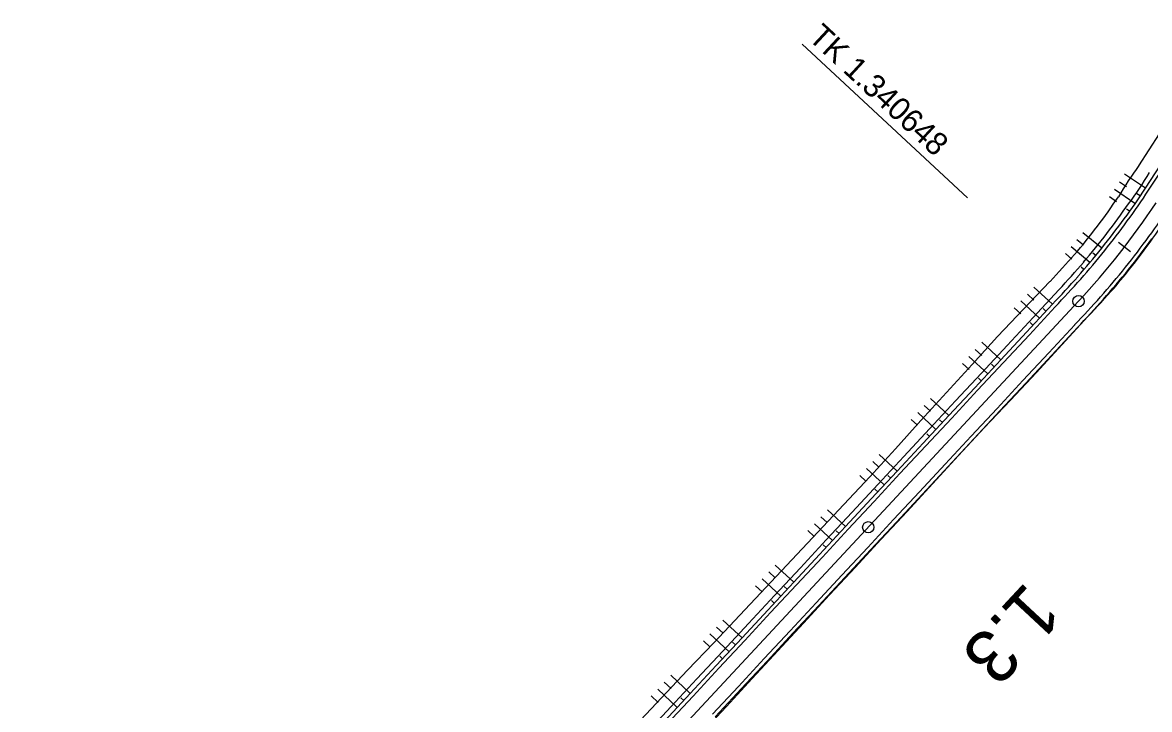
# Model space of a CAD drawing. Extents: x -481656 to -478728, y -1113199 to -1110710.
# Drawn here: x -479136.3 to -478987.9, y -1110857.1 to -1110766.6 of the extents above; entities that cross this region are included whole.
import ezdxf

# ---------------------------------------------------------------- set-up
doc = ezdxf.new("R2010")
doc.units = 0
for name, color, linetype in [('C5_HATCH_SLOPE_L', 7, 'Continuous'), ('C5_HATCH_SLOPE_R', 7, 'Continuous'), ('C5_HECTOMETRY', 7, 'Continuous'), ('C5_HLBODY', 7, 'Continuous'), ('C5_HRANA_TELESO', 7, 'Continuous'), ('C5_KORUNA', 7, 'Continuous'), ('C5_OSA', 7, 'Continuous'), ('C5_PRIKOP', 7, 'Continuous'), ('C5_STANICENI', 7, 'Continuous'), ('C5_ZPEVKRAJ', 7, 'Continuous')]:
    doc.layers.add(name, color=color, linetype=linetype)

msp = doc.modelspace()

# ---------------------------------------------------------------- linework, layer by layer
at = {"layer": 'C5_HATCH_SLOPE_L'}
for p, q in [((-478988.47, -1110788.42), (-478991.2, -1110786.61)), ((-478989.84, -1110790.47), (-478992.53, -1110788.62)), ((-478990.93, -1110788.27), (-478991.88, -1110787.64)), ((-478992.27, -1110790.25), (-478993.2, -1110789.6)), ((-478989.16, -1110789.46), (-478989.57, -1110789.18)), ((-478990.54, -1110791.47), (-478990.94, -1110791.19)), ((-478994.2, -1110796.36), (-478996.72, -1110794.34)), ((-478995.76, -1110798.24), (-478998.23, -1110796.16)), ((-478996.61, -1110795.96), (-478997.47, -1110795.26)), ((-478998.15, -1110797.78), (-478999, -1110797.05)), ((-478994.97, -1110797.3), (-478995.36, -1110796.99)), ((-478996.55, -1110799.17), (-478996.93, -1110798.84)), ((-479000.7, -1110803.73), (-479003.13, -1110801.48)), ((-479002.41, -1110805.56), (-479004.86, -1110803.28)), ((-479003.14, -1110803.17), (-479003.99, -1110802.38)), ((-479004.86, -1110804.99), (-479005.72, -1110804.19)), ((-479001.55, -1110804.65), (-479001.92, -1110804.3)), ((-479003.26, -1110806.48), (-479003.63, -1110806.14)), ((-479007.51, -1110811.06), (-479010, -1110808.74)), ((-479009.22, -1110812.89), (-479011.69, -1110810.59)), ((-479009.98, -1110810.47), (-479010.85, -1110809.67)), ((-479011.67, -1110812.31), (-479012.53, -1110811.51)), ((-479008.36, -1110811.97), (-479008.74, -1110811.63)), ((-479010.07, -1110813.8), (-479010.44, -1110813.46)), ((-479014.32, -1110818.38), (-479016.75, -1110816.12)), ((-479016.03, -1110820.21), (-479018.43, -1110817.97)), ((-479016.76, -1110817.82), (-479017.59, -1110817.05)), ((-479018.45, -1110819.66), (-479019.28, -1110818.89)), ((-479015.17, -1110819.29), (-479015.55, -1110818.95)), ((-479016.88, -1110821.13), (-479017.25, -1110820.78)), ((-479023.54, -1110825.17), (-479024.34, -1110824.43)), ((-479021.13, -1110825.7), (-479023.49, -1110823.51)), ((-479022.84, -1110827.53), (-479025.19, -1110825.35)), ((-479025.24, -1110827.01), (-479026.03, -1110826.27)), ((-479021.98, -1110826.62), (-479022.36, -1110826.27)), ((-479023.69, -1110828.45), (-479024.06, -1110828.1)), ((-479030.36, -1110832.48), (-479031.17, -1110831.73)), ((-479027.94, -1110833.02), (-479030.31, -1110830.82)), ((-479029.65, -1110834.86), (-479032.03, -1110832.64)), ((-479032.07, -1110834.3), (-479032.89, -1110833.54)), ((-479028.79, -1110833.94), (-479029.17, -1110833.59)), ((-479030.5, -1110835.77), (-479030.88, -1110835.42)), ((-479037.21, -1110839.77), (-479038.05, -1110838.99)), ((-479034.75, -1110840.35), (-479037.19, -1110838.08)), ((-479036.46, -1110842.18), (-479038.91, -1110839.9)), ((-479038.92, -1110841.59), (-479039.77, -1110840.8)), ((-479035.6, -1110841.26), (-479035.99, -1110840.91)), ((-479037.31, -1110843.09), (-479037.69, -1110842.74)), ((-479044.05, -1110847.06), (-479044.93, -1110846.25)), ((-479041.56, -1110847.67), (-479044.07, -1110845.34)), ((-479045.77, -1110848.88), (-479046.65, -1110848.06)), ((-479043.27, -1110849.5), (-479045.79, -1110847.16)), ((-479042.41, -1110848.59), (-479042.8, -1110848.23)), ((-479044.12, -1110850.42), (-479044.5, -1110850.06)), ((-479048.37, -1110854.99), (-479050.94, -1110852.6)), ((-479050.9, -1110854.35), (-479051.8, -1110853.51)), ((-479052.61, -1110856.17), (-479053.52, -1110855.32)), ((-479050.08, -1110856.82), (-479052.66, -1110854.42)), ((-479049.22, -1110855.91), (-479049.61, -1110855.55))]:
    msp.add_line(p, q, dxfattribs=at)
at = {"layer": 'C5_HATCH_SLOPE_R'}
for p, q in [((-478988.66, -1110796.55), (-478988.64, -1110796.57)), ((-478988.61, -1110796.59), (-478988.61, -1110796.59)), ((-478992.65, -1110801.54), (-478992.59, -1110801.59)), ((-478994.33, -1110803.47), (-478994.29, -1110803.5)), ((-478993.49, -1110802.51), (-478993.46, -1110802.53)), ((-478993.43, -1110802.55), (-478993.43, -1110802.55)), ((-478995.19, -1110804.41), (-478995.18, -1110804.43)), ((-478995.16, -1110804.44), (-478995.16, -1110804.44)), ((-478999.46, -1110809), (-478999.43, -1110809.02)), ((-479001.16, -1110810.83), (-479001.12, -1110810.87)), ((-479000.31, -1110809.92), (-479000.29, -1110809.93)), ((-479000.28, -1110809.95), (-479000.28, -1110809.95)), ((-479002.01, -1110811.75), (-479001.98, -1110811.77)), ((-479001.96, -1110811.79), (-479001.96, -1110811.79)), ((-479006.27, -1110816.32), (-479006.24, -1110816.35)), ((-479007.97, -1110818.15), (-479007.95, -1110818.17)), ((-479007.12, -1110817.24), (-479007.11, -1110817.25)), ((-479007.1, -1110817.26), (-479007.1, -1110817.26)), ((-479008.82, -1110819.07), (-479008.82, -1110819.07)), ((-479008.81, -1110819.08), (-479008.81, -1110819.08)), ((-479013.08, -1110823.65), (-479013.05, -1110823.67)), ((-479014.78, -1110825.48), (-479014.75, -1110825.51)), ((-479013.93, -1110824.56), (-479013.91, -1110824.57)), ((-479013.9, -1110824.59), (-479013.9, -1110824.59)), ((-479015.63, -1110826.39), (-479015.61, -1110826.41)), ((-479015.6, -1110826.43), (-479015.6, -1110826.43)), ((-479019.89, -1110830.97), (-479019.83, -1110831.02)), ((-479021.59, -1110832.8), (-479021.53, -1110832.86)), ((-479020.74, -1110831.89), (-479020.71, -1110831.91)), ((-479020.68, -1110831.94), (-479020.68, -1110831.94)), ((-479022.44, -1110833.72), (-479022.41, -1110833.75)), ((-479022.38, -1110833.77), (-479022.38, -1110833.77)), ((-479027.55, -1110839.21), (-479027.51, -1110839.24)), ((-479027.48, -1110839.27), (-479027.48, -1110839.27)), ((-479026.7, -1110838.29), (-479026.62, -1110838.36)), ((-479028.4, -1110840.12), (-479028.33, -1110840.19)), ((-479029.25, -1110841.04), (-479029.21, -1110841.07)), ((-479029.17, -1110841.11), (-479029.17, -1110841.11)), ((-479034.36, -1110846.53), (-479034.32, -1110846.57)), ((-479034.28, -1110846.61), (-479034.28, -1110846.61)), ((-479033.51, -1110845.62), (-479033.42, -1110845.69)), ((-479035.21, -1110847.45), (-479035.12, -1110847.52)), ((-479036.06, -1110848.36), (-479036.02, -1110848.4)), ((-479035.98, -1110848.44), (-479035.98, -1110848.44)), ((-479041.17, -1110853.85), (-479041.12, -1110853.9)), ((-479041.08, -1110853.94), (-479041.08, -1110853.94)), ((-479040.32, -1110852.94), (-479040.23, -1110853.02)), ((-479042.02, -1110854.77), (-479041.92, -1110854.85)), ((-479042.87, -1110855.69), (-479042.82, -1110855.73)), ((-479042.78, -1110855.77), (-479042.78, -1110855.77))]:
    msp.add_line(p, q, dxfattribs=at)
at = {"layer": 'C5_HECTOMETRY'}
msp.add_circle((-479024.94, -1110833.1), 0.75, dxfattribs=at)
at = {"layer": 'C5_HLBODY'}
msp.add_line((-479033.65, -1110769.49), (-479011.9, -1110789.71), dxfattribs=at)
msp.add_circle((-478997.26, -1110803.33), 0.75, dxfattribs=at)
at = {"layer": 'C5_HRANA_TELESO'}
for p, q in [((-478989.32, -1110785.48), (-478986.59, -1110781.28)), ((-479004.47, -1110804.34), (-479001.02, -1110800.72)), ((-479007.91, -1110807.97), (-479004.47, -1110804.34)), ((-478999.43, -1110809.02), (-478996.03, -1110805.36)), ((-479011.27, -1110811.67), (-479007.91, -1110807.97)), ((-479002.8, -1110812.72), (-478999.43, -1110809.02)), ((-479014.64, -1110815.37), (-479011.27, -1110811.67)), ((-479006.24, -1110816.35), (-479002.8, -1110812.72)), ((-479018, -1110819.06), (-479014.64, -1110815.37)), ((-479009.67, -1110819.99), (-479006.24, -1110816.35)), ((-479021.37, -1110822.76), (-479018, -1110819.06)), ((-479013.05, -1110823.67), (-479009.67, -1110819.99)), ((-479024.73, -1110826.46), (-479021.37, -1110822.76)), ((-479016.44, -1110827.34), (-479013.05, -1110823.67)), ((-479028.14, -1110830.12), (-479024.73, -1110826.46)), ((-479019.83, -1110831.02), (-479016.44, -1110827.34)), ((-479031.57, -1110833.76), (-479028.14, -1110830.12)), ((-479023.23, -1110834.69), (-479019.83, -1110831.02)), ((-479035, -1110837.4), (-479031.57, -1110833.76)), ((-479026.62, -1110838.36), (-479023.23, -1110834.69)), ((-479038.43, -1110841.03), (-479035, -1110837.4)), ((-479030.03, -1110842.02), (-479026.62, -1110838.36)), ((-479041.86, -1110844.67), (-479038.43, -1110841.03)), ((-479033.42, -1110845.69), (-479030.03, -1110842.02)), ((-479045.29, -1110848.31), (-479041.86, -1110844.67)), ((-479036.83, -1110849.36), (-479033.42, -1110845.69)), ((-479048.73, -1110851.94), (-479045.29, -1110848.31)), ((-479040.23, -1110853.02), (-479036.83, -1110849.36)), ((-479052.16, -1110855.58), (-479048.73, -1110851.94)), ((-479043.62, -1110856.69), (-479040.23, -1110853.02)), ((-479055.59, -1110859.22), (-479052.16, -1110855.58)), ((-479047.03, -1110860.35), (-479043.62, -1110856.69))]:
    msp.add_line(p, q, dxfattribs=at)
for centre, radius, start, end in [((-478950.8, -1110813.66), 47.73, 143.8045, 149.6908), ((-479070.97, -1110735.9), 95.48, 322.9287, 325.7936), ((-479070.67, -1110735.46), 95.51, 319.7497, 322.6145), ((-479070.67, -1110735.48), 102.31, 322.6103, 325.4751), ((-479210.78, -1110605.51), 286.54, 317.0581, 318.0186), ((-479070.62, -1110735.4), 102.33, 319.6909, 322.5557), ((-479220.96, -1110596.42), 307, 317.1107, 318.0626)]:
    msp.add_arc(centre, radius, start, end, dxfattribs=at)
at = {"layer": 'C5_KORUNA'}
for p, q in [((-478988.47, -1110788.42), (-478985.71, -1110784.25)), ((-479004.11, -1110807.4), (-479000.7, -1110803.73)), ((-479007.51, -1110811.06), (-479004.11, -1110807.4)), ((-479000.81, -1110810.46), (-478997.41, -1110806.8)), ((-479010.92, -1110814.72), (-479007.51, -1110811.06)), ((-479004.22, -1110814.12), (-479000.81, -1110810.46)), ((-479014.32, -1110818.38), (-479010.92, -1110814.72)), ((-479007.62, -1110817.78), (-479004.22, -1110814.12)), ((-479017.73, -1110822.04), (-479014.32, -1110818.38)), ((-479011.03, -1110821.44), (-479007.62, -1110817.78)), ((-479014.43, -1110825.1), (-479011.03, -1110821.44)), ((-479021.13, -1110825.7), (-479017.73, -1110822.04)), ((-479024.54, -1110829.36), (-479021.13, -1110825.7)), ((-479017.84, -1110828.77), (-479014.43, -1110825.1)), ((-479021.24, -1110832.43), (-479017.84, -1110828.77)), ((-479027.94, -1110833.02), (-479024.54, -1110829.36)), ((-479031.35, -1110836.69), (-479027.94, -1110833.02)), ((-479024.65, -1110836.09), (-479021.24, -1110832.43)), ((-479028.05, -1110839.75), (-479024.65, -1110836.09)), ((-479034.75, -1110840.35), (-479031.35, -1110836.69)), ((-479038.16, -1110844.01), (-479034.75, -1110840.35)), ((-479031.46, -1110843.41), (-479028.05, -1110839.75)), ((-479034.86, -1110847.07), (-479031.46, -1110843.41)), ((-479041.56, -1110847.67), (-479038.16, -1110844.01)), ((-479044.97, -1110851.33), (-479041.56, -1110847.67)), ((-479038.27, -1110850.74), (-479034.86, -1110847.07)), ((-479041.67, -1110854.4), (-479038.27, -1110850.74)), ((-479048.37, -1110854.99), (-479044.97, -1110851.33)), ((-479051.78, -1110858.66), (-479048.37, -1110854.99)), ((-479045.08, -1110858.06), (-479041.67, -1110854.4))]:
    msp.add_line(p, q, dxfattribs=at)
for centre, radius, start, end in [((-479030.11, -1110762.84), 48.88, 322.6803, 328.434), ((-479070.49, -1110735.23), 97.75, 321.2966, 324.1614), ((-479070.49, -1110735.23), 102.25, 321.2966, 324.1614), ((-479070.49, -1110735.23), 97.75, 318.4318, 321.2966), ((-479070.49, -1110735.23), 102.25, 318.4318, 321.2966), ((-479214.86, -1110603.41), 293.25, 316.9114, 317.878), ((-479221.5, -1110597.32), 306.75, 316.9304, 317.8742)]:
    msp.add_arc(centre, radius, start, end, dxfattribs=at)
at = {"layer": 'C5_OSA'}
msp.add_line((-479231.87, -1111055.62), (-478997.26, -1110803.33), dxfattribs=at)
msp.add_arc((-479070.49, -1110735.23), 100, 317.0793, 326.545, dxfattribs=at)
at = {"layer": 'C5_PRIKOP'}
for p, q in [((-479003.24, -1110805.48), (-478999.84, -1110801.82)), ((-479006.65, -1110809.14), (-479003.24, -1110805.48)), ((-479010.05, -1110812.8), (-479006.65, -1110809.14)), ((-479013.45, -1110816.47), (-479010.05, -1110812.8)), ((-479016.86, -1110820.13), (-479013.45, -1110816.47)), ((-479020.26, -1110823.79), (-479016.86, -1110820.13)), ((-479023.67, -1110827.45), (-479020.26, -1110823.79)), ((-479027.07, -1110831.11), (-479023.67, -1110827.45)), ((-479030.48, -1110834.77), (-479027.07, -1110831.11)), ((-479033.88, -1110838.44), (-479030.48, -1110834.77)), ((-479037.29, -1110842.1), (-479033.88, -1110838.44)), ((-479040.69, -1110845.76), (-479037.29, -1110842.1)), ((-479044.1, -1110849.42), (-479040.69, -1110845.76)), ((-479047.5, -1110853.08), (-479044.1, -1110849.42)), ((-479050.91, -1110856.74), (-479047.5, -1110853.08)), ((-479054.31, -1110860.41), (-479050.91, -1110856.74))]:
    msp.add_line(p, q, dxfattribs=at)
for centre, radius, start, end in [((-479029.62, -1110761.53), 48.54, 323.3654, 329.1948), ((-479070.49, -1110735.23), 97.08, 322.4379, 325.3027), ((-479070.49, -1110735.23), 97.08, 319.5731, 322.4379), ((-479215.19, -1110605.74), 291.25, 317.6812, 318.6398)]:
    msp.add_arc(centre, radius, start, end, dxfattribs=at)
at = {"layer": 'C5_STANICENI'}
msp.add_line((-478990.43, -1110796.81), (-478992.01, -1110795.59), dxfattribs=at)
at = {"layer": 'C5_ZPEVKRAJ'}
for p, q in [((-478988.05, -1110788.7), (-478985.3, -1110784.53)), ((-479003.74, -1110807.74), (-479000.34, -1110804.07)), ((-479001.18, -1110810.12), (-478997.77, -1110806.46)), ((-479007.15, -1110811.4), (-479003.74, -1110807.74)), ((-479004.58, -1110813.78), (-479001.18, -1110810.12)), ((-479010.55, -1110815.06), (-479007.15, -1110811.4)), ((-479007.99, -1110817.44), (-479004.58, -1110813.78)), ((-479013.96, -1110818.72), (-479010.55, -1110815.06)), ((-479011.39, -1110821.1), (-479007.99, -1110817.44)), ((-479017.36, -1110822.38), (-479013.96, -1110818.72)), ((-479014.8, -1110824.77), (-479011.39, -1110821.1)), ((-479020.77, -1110826.04), (-479017.36, -1110822.38)), ((-479018.2, -1110828.43), (-479014.8, -1110824.77)), ((-479024.17, -1110829.7), (-479020.77, -1110826.04)), ((-479021.61, -1110832.09), (-479018.2, -1110828.43)), ((-479027.58, -1110833.37), (-479024.17, -1110829.7)), ((-479025.01, -1110835.75), (-479021.61, -1110832.09)), ((-479030.98, -1110837.03), (-479027.58, -1110833.37)), ((-479028.42, -1110839.41), (-479025.01, -1110835.75)), ((-479034.39, -1110840.69), (-479030.98, -1110837.03)), ((-479037.79, -1110844.35), (-479034.39, -1110840.69)), ((-479031.82, -1110843.07), (-479028.42, -1110839.41)), ((-479035.23, -1110846.73), (-479031.82, -1110843.07)), ((-479041.2, -1110848.01), (-479037.79, -1110844.35)), ((-479044.6, -1110851.67), (-479041.2, -1110848.01)), ((-479038.63, -1110850.4), (-479035.23, -1110846.73)), ((-479042.04, -1110854.06), (-479038.63, -1110850.4)), ((-479048.01, -1110855.33), (-479044.6, -1110851.67)), ((-479045.44, -1110857.72), (-479042.04, -1110854.06)), ((-479051.41, -1110859), (-479048.01, -1110855.33))]:
    msp.add_line(p, q, dxfattribs=at)
for centre, radius, start, end in [((-479029.91, -1110762.98), 49.12, 322.682, 328.4306), ((-479028.47, -1110763.97), 50.88, 322.693, 328.4079), ((-479070.49, -1110735.23), 98.25, 321.2966, 324.1614), ((-479070.49, -1110735.23), 101.75, 321.2966, 324.1614), ((-479070.49, -1110735.23), 98.25, 318.4318, 321.2966), ((-479070.49, -1110735.23), 101.75, 318.4318, 321.2966), ((-479215.6, -1110602.73), 294.75, 316.9136, 317.8775), ((-479220.76, -1110598), 305.25, 316.9283, 317.8746)]:
    msp.add_arc(centre, radius, start, end, dxfattribs=at)

# ---------------------------------------------------------------- texts
at = {"layer": 'C5_HECTOMETRY'}
msp.add_text('1.3', height=7, rotation=227.0337, dxfattribs=at).set_placement((-479004.13, -1110840.1))
at = {"layer": 'C5_HLBODY'}
msp.add_text('TK 1.340648', height=2.999, rotation=317.0793, dxfattribs=at).set_placement((-479032.97, -1110768.76))

doc.saveas('drawing.dxf')
